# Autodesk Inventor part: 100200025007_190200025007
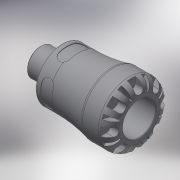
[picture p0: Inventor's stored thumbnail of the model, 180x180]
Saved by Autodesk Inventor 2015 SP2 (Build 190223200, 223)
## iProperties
Created: 2016-12
Part Number: 100200025007_190200025007
Material: Generic
Description: PLASSON MALE ADAPTOR 25X3/4" SERIES 1
Document SubType Name: Modeling
Designer: KIM
Mass: 447.839 g
Surface Area: 722.341 cm^2
Volume: 447.839 cm^3
Density: 1 g/cm^3
Appearance: Default
Author: KIM
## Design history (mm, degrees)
derived "1002.ipt"
feature "Solid1::1002.ipt"
tag "TaggingFeature1"
body "Solid1"
other parameters: "d0" = 76, "d1" = 20.16, "d2" = 25, "d3" = 31.25, "d4" = 47, "d6" = 48, "d8" = 39.95, "d13" = 6.3, "d14" = 6.3, "d15" = 0, "d17" = 360 deg, "d19" = 8 deg, "d20" = 0.5, "d21" = 0.5, "d22" = 8 deg, "d24" = 0, "d26" = 360 deg, "d32" = 0.925, "d33" = 4.7, "d34" = 26.441, "d35" = 3.125, "d38" = 17, "d39" = 0.79323, "d42" = 8.75, "d43" = 5.75, "d45" = 12.348, "d46" = 0, "d59" = 360 deg, "d61" = 7.4375, "d62" = 0.5, "d64" = 0, "d65" = 0.47, "d_" = 25, "E_" = 47, "H_" = 76, "l_" = 48, "R_" = 26.441, "l_2" = 17, "d9" = 7.875, "d11" = 47, "d12" = 31.25
